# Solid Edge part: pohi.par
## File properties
Author: Andris
Template: Normal.par
Last saved by: Andris
Revision: 34
Application: Solid Edge
Face Style: Steel
Coef. of Thermal Exp: 0.0
Thermal Conductivity: 0.0
Specific Heat: 0.0
Modulus of Elasticity: 0.0
Poission's Ratio: 0.0
Yield Stress: 0.0
Ultimate Stress: 0.0
Elongation: 0.0
Accuracy: 0,990
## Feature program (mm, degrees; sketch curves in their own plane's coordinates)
make body feature "unnamed MakeBodyFeature 1"
thinwall "Thinwall_3"  Thickness = 3 mm
web network "WebNetwork_15"  Thickness = 1.5 mm
web network "WebNetwork_16"  Thickness = 1.5 mm
web network "WebNetwork_25"  Thickness = 0.25 mm
web network "WebNetwork_26"  Thickness = 0.25 mm
web network "WebNetwork_28"  Thickness = 0.25 mm
sketch for "ExtrudedCutout_6" plane through (0, 0, 24) normal (0, 0, 1) x-axis (1, 0, 0)
  bspline degree 3 poles (87.4419, -30) (113.697, -31.8378) (134.3333, -30.1711) (149.3508, -25) knots 0 1 multiplicities 4 4
  line (149.3508, 25) -> (149.3508, -25)
  bspline degree 3 poles (87.4419, 30) (113.697, 31.8378) (134.3333, 30.1711) (149.3508, 25) knots 0 1 multiplicities 4 4
  line (87.4419, 30) -> (87.4419, -30)
extrude "ExtrudedCutout_6" cut finite 34 along +normal
web network "WebNetwork_29"  Thickness = 0.25 mm
sketch for "ExtrudedProtrusion_5" plane through (0, 0, 0) normal (0, -1, 0) x-axis (1, 0, 0)
  bspline degree 3 poles (337.431, -24.5227) (338.411, -24.0381) (341.9173, -22.343) (343.844, -13.0795) (352.3372, -4.6896) (365.9993, -5.0636) (368.0449, 2.9356) (368.8697, 6.7546) knots 0 0.0636 0.2535 0.5392 0.7728 1 multiplicities 4 1 1 1 1 4
  bspline degree 3 poles (328.1156, 6.0499) (337.5399, 8.443) (351.1246, 8.6779) (368.8697, 6.7546) knots 0 1 multiplicities 4 4
  bspline degree 3 poles (328.1156, 6.0499) (320.4333, -5.77) (317.9222, -16.1755) (320.5825, -25.1666) knots 0 1 multiplicities 4 4
  bspline degree 3 poles (320.5825, -25.1666) (321.5429, -26.5521) (327.1591, -26.3375) (337.431, -24.5227) knots 0 1 multiplicities 4 4
extrude "ExtrudedProtrusion_5" add finite 4 symmetric
fillet "Round_2" radius 1
sketch for "unnamed Protrusion 1" plane through (0, 0, 22.3781) normal (0, 0, 1) x-axis (1, 0, 0)
  circle centre (349.7572, 0) radius 3.0223
extrude "unnamed Protrusion 1" add to key point along -normal
sketch for "ExtrudedCutout_9" plane through (126.5215, 0.285, 38.0033) normal (0, 0, 1) x-axis (0, 1, 0)
  line (37.215, -45.0064) -> (-37.785, -45.0064)
  line (-37.785, -45.0064) -> (-37.785, -204.2864)
  line (-37.785, -204.2864) -> (37.215, -204.2864)
  line (37.215, -204.2864) -> (37.215, -45.0064)
extrude "ExtrudedCutout_9" cut finite 0.05 along -normal
sketch for "unnamed Cutout 1" plane through (126.5215, 0.285, 38.0033) normal (0, 0, 1) x-axis (0, 1, 0)
  circle centre (-0.285, 69.0662) radius 5
extrude "unnamed Cutout 1" cut finite 13.3833 along -normal
sketch for "ExtrudedProtrusion_9" plane through (0, 0, 0) normal (0, -1, 0) x-axis (1, 0, 0)
  line (144.6164, 33.4887) -> (144.6164, 32.3387)
  line (144.6164, 32.3387) -> (143.4664, 32.3387)
  line (143.4664, 32.3387) -> (143.4664, 31.1887)
  line (143.4664, 31.1887) -> (142.3164, 31.1887)
  line (142.3164, 31.1887) -> (142.3164, 30.0387)
  line (142.3164, 30.0387) -> (141.1664, 30.0387)
  line (141.1664, 30.0387) -> (141.1664, 28.8887)
  line (141.1664, 28.8887) -> (140.0164, 28.8887)
  line (140.0164, 28.8887) -> (140.0164, 27.7387)
  line (140.0164, 27.7387) -> (138.8664, 27.7387)
  line (138.8664, 27.7387) -> (138.8664, 26.5887)
  line (138.8664, 26.5887) -> (137.7164, 26.5887)
  line (137.7164, 26.5887) -> (137.7164, 25.4387)
  line (137.7164, 25.4387) -> (136.5692, 25.3587)
  line (136.5692, 25.3587) -> (136.5692, 24.2087)
  line (136.5692, 24.2087) -> (135.4192, 24.2087)
  line (135.4192, 24.2087) -> (135.4192, 23.0587)
  line (135.4192, 23.0587) -> (134.2692, 23.0587)
  line (134.2692, 23.0587) -> (134.2692, 21.9087)
  line (134.2692, 21.9087) -> (133.1192, 21.9087)
  line (133.1192, 21.9087) -> (133.1192, 20.7587)
  line (133.1192, 20.7587) -> (131.9692, 20.7587)
  line (131.9692, 20.7587) -> (131.9692, 19.6087)
  line (131.9692, 19.6087) -> (130.8192, 19.6087)
  line (130.8192, 19.6087) -> (130.8192, 18.4587)
  line (130.8192, 18.4587) -> (129.6692, 18.4587)
  line (129.6692, 18.4587) -> (129.6692, 17.4676)
  line (129.6692, 17.4676) -> (131.8801, 17.4676)
  line (131.8801, 17.4676) -> (150.3126, 35.9237)
  line (150.3126, 35.9237) -> (150.3126, 37.7533)
  line (149.2164, 37.7533) -> (150.3126, 37.7533)
  line (149.2164, 36.9387) -> (149.2164, 37.7533)
  line (149.2164, 36.9387) -> (148.0664, 36.9387)
  line (148.0664, 36.9387) -> (148.0664, 35.7887)
  line (148.0664, 35.7887) -> (146.9164, 35.7887)
  line (146.9164, 35.7887) -> (146.9164, 34.6387)
  line (146.9164, 34.6387) -> (145.7664, 34.6387)
  line (145.7664, 34.6387) -> (145.7664, 33.4887)
  line (145.7664, 33.4887) -> (144.6164, 33.4887)
extrude "ExtrudedProtrusion_9" add finite 13.9584 symmetric
sketch for "unnamed Cutout 2" plane through (67.7189, 0, 27.0743) normal (1, 0, 0) x-axis (0, 1, 0)
  line (9.9594, 3.2497) -> (9.9594, -9.2161)
  line (9.9594, -9.2161) -> (-3.0291, -9.2161)
  line (-3.0291, -9.2161) -> (-3.0291, 3.2497)
  line (-3.0291, 3.2497) -> (9.9594, 3.2497)
extrude "unnamed Cutout 2" cut finite 8.1808 along -normal
swept protrusion "unnamed SweptProtrusion 1"
mirror "unnamed Mirror 1" of "unnamed SweptProtrusion 1" about plane through (0, 0, 0) normal (0, -1, 0)
swept protrusion "unnamed SweptProtrusion 2"
swept protrusion "unnamed SweptProtrusion 3"
mirror "unnamed Mirror 2" of "unnamed SweptProtrusion 3" about plane through (0, 0, 0) normal (0, -1, 0)
swept protrusion "unnamed SweptProtrusion 4"
swept protrusion "unnamed SweptProtrusion 5"
swept protrusion "unnamed SweptProtrusion 6"
fillet "Round_4" radius 0.1
sketch for "ExtrudedProtrusion_12" plane through (0, 0, 0) normal (0, -1, 0) x-axis (1, 0, 0)
  bspline degree 3 poles (396.5922, 55.3222) (394.4681, 54.8016) (389.5714, 53.7515) (380.5774, 51.7434) (374.6623, 53.8894) (371.442, 55.081) knots 0 0.2319 0.6336 1 multiplicities 4 1 1 4
  line (367.383, 45.995) -> (371.442, 55.081)
  bspline degree 3 poles (393.0457, 44.1347) (390.4923, 43.7584) (385.5994, 43.1851) (376.3891, 42.1056) (370.797, 44.5191) (367.383, 45.995) knots 0 0.2684 0.6132 1 multiplicities 4 1 1 4
  line (396.5922, 55.3222) -> (393.0457, 44.1347)
extrude "ExtrudedProtrusion_12" add finite 1 symmetric
fillet "Round_5" radius 1
swept protrusion "unnamed SweptProtrusion 7"
swept protrusion "unnamed SweptProtrusion 8"
sketch for "unnamed Protrusion 2" plane through (0, 0, 57.9154) normal (0, 0, 1) x-axis (1, 0, 0)
  circle centre (0, -62.5557) radius 0.25
extrude "unnamed Protrusion 2" add through along -normal
sketch for "unnamed Protrusion 3" plane through (0, 0, 57.9154) normal (0, 0, 1) x-axis (1, 0, 0)
  circle centre (-34.6227, -43.2731) radius 0.2486
extrude "unnamed Protrusion 3" add through along -normal
sketch for "unnamed Protrusion 4" plane through (0, 0, 57.9154) normal (0, 0, 1) x-axis (1, 0, 0)
  circle centre (-73.0716, -16.4479) radius 0.255
extrude "unnamed Protrusion 4" add through along -normal
sketch for "ExtrudedProtrusion_17" plane through (0, 0, 57.9154) normal (0, 0, 1) x-axis (1, 0, 0)
  circle centre (-94.4493, 0) radius 0.25
extrude "ExtrudedProtrusion_17" add finite 6.8378 along -normal
sketch for "unnamed Protrusion 5" plane through (0, 0, 57.9154) normal (0, 0, 1) x-axis (1, 0, 0)
  circle centre (-73.0716, 16.4785) radius 0.2335
extrude "unnamed Protrusion 5" add through along -normal
sketch for "unnamed Protrusion 6" plane through (0, 0, 57.9154) normal (0, 0, 1) x-axis (1, 0, 0)
  circle centre (-34.6227, 43.2659) radius 0.2421
extrude "unnamed Protrusion 6" add through along -normal
sketch for "unnamed Protrusion 7" plane through (0, 0, 57.9154) normal (0, 0, 1) x-axis (1, 0, 0)
  circle centre (0, 62.5557) radius 0.25
extrude "unnamed Protrusion 7" add through along -normal
sketch for "ExtrudedProtrusion_21" plane through (251.1679, 0, 37.9533) normal (0, 0, 1) x-axis (0, 1, 0)
  line (-26.457, -37.5232) -> (-26.457, -70.8681)
  line (-26.457, -70.8681) -> (-20.2217, -70.8681)
  line (-20.2217, -70.8681) -> (-20.2217, -37.5232)
  line (-20.2217, -37.5232) -> (-26.457, -37.5232)
extrude "ExtrudedProtrusion_21" add finite 3.4865 along +normal
sketch for "ExtrudedProtrusion_22" plane through (251.1679, 0, 37.9533) normal (0, 0, 1) x-axis (0, 1, 0)
  line (-26.457, 2.8702) -> (-26.457, -32.9146)
  line (-26.457, -32.9146) -> (-20.2217, -32.9146)
  line (-20.2217, -32.9146) -> (-20.2217, 2.8702)
  line (-20.2217, 2.8702) -> (-26.457, 2.8702)
extrude "ExtrudedProtrusion_22" add finite 4.2133 along +normal
sketch for "unnamed Cutout 3" plane through (322.0361, -23.3393, 39.6965) normal (1, 0, 0) x-axis (0, 1, 0)
  line (3.1176, 2.47) -> (-1.0195, 2.47)
  line (-1.0195, 2.47) -> (-0.5942, 0.432)
  line (-0.5942, 0.432) -> (3.1176, 0.432)
  line (3.1176, 0.432) -> (3.1176, 2.47)
extrude "unnamed Cutout 3" cut to key point along -normal
mirror "unnamed Mirror 3" of "ExtrudedProtrusion_22", "ExtrudedProtrusion_21" about plane through (0, 0, 0) normal (0, -1, 0)
extrude "unnamed Protrusion 8" add finite 3.4865
extrude "unnamed Protrusion 9" add finite 4.2133
sketch for "ExtrudedCutout_14" plane through (322.0361, 23.3393, 39.6965) normal (1, 0, 0) x-axis (0, 1, 0)
  line (-3.1176, 2.5601) -> (0.992, 2.47)
  line (0.992, 2.47) -> (0.352, -0.3474)
  line (0.352, -0.3474) -> (-3.1176, -0.3474)
  line (-3.1176, -0.3474) -> (-3.1176, 2.5601)
extrude "ExtrudedCutout_14" cut finite 77.5633 along -normal
sketch for "ExtrudedProtrusion_26" plane through (251.1679, 0, 37.9533) normal (0, 0, 1) x-axis (0, 1, 0)
  line (0, 0) -> (0, 0)
  line (-12.3838, 66.7579) -> (-12.3838, 51.8392)
  line (-12.3838, 51.8392) -> (-17.3567, 51.8392)
  line (-17.3567, 51.8392) -> (-17.3567, 70.7983)
  line (-17.3567, 70.7983) -> (14.8116, 70.7983)
  line (14.8116, 70.7983) -> (14.8116, 51.8392)
  line (14.8116, 51.8392) -> (10.4604, 51.8392)
  line (10.4604, 51.8392) -> (10.4604, 66.7579)
  line (10.4604, 66.7579) -> (-12.3838, 66.7579)
extrude "ExtrudedProtrusion_26" add finite 3.3812 along +normal
chamfer "Chamfer_3" setback 1
chamfer "Chamfer_4" setback 1
chamfer "Chamfer_5" setback 1
sketch for "ExtrudedProtrusion_27" plane through (183.9101, -0.9617, 40.8345) normal (0.707107, 0, 0.707107) x-axis (0, 1, 0)
  circle centre (-1.8733, -0.0212) radius 0.3196
extrude "ExtrudedProtrusion_27" add finite 0.3565 along +normal
sketch for "ExtrudedProtrusion_28" #1 plane through (184.1771, -2.8351, 41.0716) normal (0.707107, 0, 0.707107) x-axis (0, -1, 0)
  circle centre (0, 0) radius 2.5331
sketch for "ExtrudedProtrusion_28" #2 plane through (184.1771, -2.8351, 41.0716) normal (0.707107, 0, 0.707107) x-axis (0, -1, 0)
  arc centre (0, 0) radius 2.1861 from (-1.562, -1.5295) to (-2.1861, 0) cw
  line (-2.1861, 0) -> (-0.3136, 0)
  arc centre (0, 0) radius 0.3136 from (-0.3136, 0) to (-0.235, 0.2076) cw
  line (-0.235, 0.2076) -> (-1.6382, 1.4475)
  arc centre (0, 0) radius 2.1861 from (-1.6382, 1.4475) to (0, 2.1861) cw
  line (0, 2.1861) -> (0, 0.3136)
  line (1.562, 1.5295) -> (0.2241, 0.2194)
  arc centre (0, 0) radius 2.1861 from (1.562, 1.5295) to (2.1861, 0) cw
  line (0.3136, 0) -> (2.1861, 0)
  arc centre (0, 0) radius 0.3136 from (0.3136, 0) to (0.235, -0.2076) cw
  line (1.6382, -1.4475) -> (0.235, -0.2076)
  line (0, -0.3136) -> (0, -2.1861)
  arc centre (0, 0) radius 0.3136 from (0, -0.3136) to (-0.2241, -0.2194) cw
  line (-0.2241, -0.2194) -> (-1.562, -1.5295)
extrude "ExtrudedProtrusion_28" add finite 0.4112 along +normal
sketch used by "ExtrudedProtrusion_29" plane through (251.1679, 0, 39.789) normal (0, 0, 1) x-axis (0, 1, 0)
extrude "ExtrudedProtrusion_29" add finite 1 along +normal
sketch for "ExtrudedProtrusion_30" plane through (251.1679, 0, 39.789) normal (0, 0, 1) x-axis (0, 1, 0)
extrude "ExtrudedProtrusion_30" add finite 1 along +normal
sketch for "unnamed Protrusion 10" #1 plane through (266.1901, -14.5079, 39.789) normal (0, 0, -1) x-axis (-1, 0, 0)
  circle centre (14.8241, 0) radius 0.594
sketch for "unnamed Protrusion 10" #2 plane through (266.1901, -14.5079, 39.789) normal (0, 0, -1) x-axis (-1, 0, 0)
  circle centre (-13.1449, 0) radius 0.594
sketch for "unnamed Protrusion 10" #3 plane through (266.1901, -14.5079, 39.789) normal (0, 0, -1) x-axis (-1, 0, 0)
  circle centre (-26.2635, 0) radius 0.594
sketch for "unnamed Protrusion 10" #4 plane through (266.1901, -14.5079, 39.789) normal (0, 0, -1) x-axis (-1, 0, 0)
  circle centre (-54.2325, 0) radius 0.594
extrude "unnamed Protrusion 10" add through along +normal
mirror "unnamed Mirror 4" of "ExtrudedProtrusion_30" about plane through (0, 0, 0) normal (0, -1, 0)
extrude "unnamed Protrusion 11" add finite 1
mirror "unnamed Mirror 5" of "unnamed Protrusion 10" about plane through (0, 0, 0) normal (0, -1, 0)
extrude "unnamed Protrusion 12" add through
mirror "unnamed Mirror 6" of "ExtrudedProtrusion_29" about plane through (0, 0, 0) normal (0, -1, 0)
extrude "unnamed Protrusion 13" add finite 1
sketch used by "unnamed Cutout 4" plane through (315.6066, 0, 0) normal (1, 0, 0) x-axis (0, 1, 0)
extrude "unnamed Cutout 4" cut finite 25 along -normal
mirror "unnamed Mirror 7" of "unnamed Cutout 4" about plane through (0, 0, 0) normal (0, -1, 0)
extrude "unnamed Cutout 5" cut finite 25
sketch for "unnamed Protrusion 14" #1 plane through (315.6066, 0, 0) normal (1, 0, 0) x-axis (0, 1, 0)
  circle centre (-18.1573, 7.4973) radius 2
sketch for "unnamed Protrusion 14" #2 plane through (315.6066, 0, 0) normal (1, 0, 0) x-axis (0, 1, 0)
  circle centre (18.1573, 7.4973) radius 2
extrude "unnamed Protrusion 14" add finite 34.9716 symmetric
sketch for "unnamed Protrusion 15" plane through (333.0923, -18.1573, 7.4973) normal (1, 0, 0) x-axis (0, 1, 0)
  arc centre (0, 0) radius 5.4358 from (5.4358, 0) to (4.0074, -3.6726) cw
  line (1.4745, -1.3513) -> (4.0074, -3.6726)
  arc centre (0, 0) radius 2 from (1.4745, -1.3513) to (0, -2) cw
  line (0, -5.4358) -> (0, -2)
  arc centre (0, 0) radius 5.4358 from (0, -5.4358) to (-3.5666, -4.1021) cw
  line (-1.3123, -1.5093) -> (-3.5666, -4.1021)
  line (-5.4358, 0) -> (-2, 0)
  line (-4.0074, 3.6726) -> (-1.4745, 1.3513)
  arc centre (0, 0) radius 2 from (-1.4745, 1.3513) to (0, 2) cw
  line (0, 2) -> (0, 5.4358)
  arc centre (0, 0) radius 5.4358 from (0, 5.4358) to (3.5666, 4.1021) cw
  line (3.5666, 4.1021) -> (1.3123, 1.5093)
  arc centre (0, 0) radius 2 from (1.3123, 1.5093) to (2, 0) cw
  line (2, 0) -> (5.4358, 0)
extrude "unnamed Protrusion 15" add finite 1 along -normal
mirror "unnamed Mirror 8" of "unnamed Protrusion 15" about plane through (0, 0, 0) normal (0, -1, 0)
extrude "unnamed Protrusion 16" add finite 1
fillet "Round_10" radius 1
fillet "Round_11" radius 1
fillet "Round_14" radius 0.75
fillet "Round_15" radius 0.75
chamfer "Chamfer_7" setback 1
chamfer "Chamfer_8" setback 1
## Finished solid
Body 1: solid body, 331 faces, 823 edges, 505 vertices, 2 separate solids.
  Faces by surface: plane 204, cylinder 68, blend 20, spline 12, torus 12, swept 9, sphere 4, offset 2
  Edges by curve: line 450, circle 160, intersection 159, curve on surface 22, ellipse 17, spline 15
Body 2: solid body, 8 faces, 22 edges, 16 vertices.
  Faces by surface: spline 8
  Edges by curve: curve on surface 19, spline 3
Bounding box of the edges (mm; curved faces can reach further): 493.712 x 159.470 x 84.233, from (-97.1195, -78.9981, -26.0672) to (396.5922, 80.4718, 58.1654).
Cylindrical faces by radius (mm): R0.125 x1, R0.2335 x1, R0.2421 x1, R0.2486 x1, R0.25 x3, R0.255 x1, R0.3136 x4, R0.3196 x1, R0.35 x2, R0.375 x4, R0.594 x8, R1 x3, R2 x6, R2.1861 x4, R2.5331 x1, R3 x16, R3.0223 x2, R5 x1, R5.4358 x8
Toroidal faces (ring radius, tube radius in mm): R0.025 r0.1 x1, R0.845 r0.375 x1, R1.9122 r0.35 x2, R1.9917 r0.375 x1, R2.1636 r0.375 x4, R2.2989 r0.375 x1, R3.9881 r0.35 x2
Spherical faces by radius (mm): R1 x4
Planar faces by outward normal: +x 24, +y 17, +z 46, -x 42, -y 18, -z 11, oblique 46
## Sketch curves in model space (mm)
arc centre (333.0923, -18.1573, 7.4973) radius 2 from (333.0923, -16.6828, 6.146) through (333.0923, -17.3518, 5.6666) to (333.0923, -18.1573, 5.4973)
line (333.0923, -16.6828, 6.146) -> (333.0923, -14.1498, 3.8246)
arc centre (333.0923, -18.1573, 7.4973) radius 5.4358 from (333.0923, -12.7215, 7.4973) through (333.0923, -13.0911, 5.527) to (333.0923, -14.1498, 3.8246)
line (333.0923, -16.1573, 7.4973) -> (333.0923, -12.7215, 7.4973)
arc centre (333.0923, -18.1573, 7.4973) radius 2 from (333.0923, -16.845, 9.0066) through (333.0923, -16.3373, 8.3266) to (333.0923, -16.1573, 7.4973)
line (333.0923, -14.5907, 11.5994) -> (333.0923, -16.845, 9.0066)
arc centre (333.0923, -18.1573, 7.4973) radius 5.4358 from (333.0923, -18.1573, 12.9331) through (333.0923, -16.2534, 12.5887) to (333.0923, -14.5907, 11.5994)
line (333.0923, -18.1573, 9.4973) -> (333.0923, -18.1573, 12.9331)
arc centre (333.0923, -18.1573, 7.4973) radius 2 from (333.0923, -19.6317, 8.8486) through (333.0923, -18.9627, 9.3279) to (333.0923, -18.1573, 9.4973)
line (333.0923, -22.1647, 11.1699) -> (333.0923, -19.6317, 8.8486)
arc centre (333.0923, -18.1573, 7.4973) radius 5.4358 from (333.0923, -23.5931, 7.4973) through (333.0923, -23.2234, 9.4676) to (333.0923, -22.1647, 11.1699)
line (333.0923, -23.5931, 7.4973) -> (333.0923, -20.1573, 7.4973)
arc centre (333.0923, -18.1573, 7.4973) radius 2 from (333.0923, -19.4695, 5.988) through (333.0923, -19.9772, 6.668) to (333.0923, -20.1573, 7.4973)
line (333.0923, -19.4695, 5.988) -> (333.0923, -21.7239, 3.3952)
arc centre (333.0923, -18.1573, 7.4973) radius 5.4358 from (333.0923, -18.1573, 2.0615) through (333.0923, -20.0612, 2.4058) to (333.0923, -21.7239, 3.3952)
line (333.0923, -18.1573, 2.0615) -> (333.0923, -18.1573, 5.4973)
arc centre (281.0825, -14.9748, 39.789) radius 3 from (281.0825, -17.9748, 39.789) through (283.2647, -17.0335, 39.789) to (284.0825, -14.9748, 39.789)
line (284.0825, -14.9748, 39.789) -> (284.0825, -14.0411, 39.789)
arc centre (281.0825, -14.0411, 39.789) radius 3 from (281.0825, -11.0411, 39.789) through (283.2647, -11.9824, 39.789) to (284.0825, -14.0411, 39.789)
line (281.0825, -11.0411, 39.789) -> (251.2978, -11.0411, 39.789)
arc centre (251.2978, -14.0411, 39.789) radius 3 from (251.2978, -11.0411, 39.789) through (249.1156, -11.9824, 39.789) to (248.2978, -14.0411, 39.789)
line (248.2978, -14.0411, 39.789) -> (248.2978, -14.9748, 39.789)
arc centre (251.2978, -14.9748, 39.789) radius 3 from (251.2978, -17.9748, 39.789) through (249.1156, -17.0335, 39.789) to (248.2978, -14.9748, 39.789)
line (251.2978, -17.9748, 39.789) -> (281.0825, -17.9748, 39.789)
arc centre (290.9237, -14.9748, 39.789) radius 3 from (290.9237, -17.9748, 39.789) through (288.7416, -17.0335, 39.789) to (287.9237, -14.9748, 39.789)
line (287.9237, -14.9748, 39.789) -> (287.9237, -14.0411, 39.789)
arc centre (290.9237, -14.0411, 39.789) radius 3 from (290.9237, -11.0411, 39.789) through (288.7416, -11.9824, 39.789) to (287.9237, -14.0411, 39.789)
line (290.9237, -11.0411, 39.789) -> (320.7084, -11.0411, 39.789)
arc centre (320.7084, -14.0411, 39.789) radius 3 from (320.7084, -11.0411, 39.789) through (322.8906, -11.9824, 39.789) to (323.7084, -14.0411, 39.789)
line (323.7084, -14.0411, 39.789) -> (323.7084, -14.9748, 39.789)
arc centre (320.7084, -14.9748, 39.789) radius 3 from (320.7084, -17.9748, 39.789) through (322.8906, -17.0335, 39.789) to (323.7084, -14.9748, 39.789)
line (320.7084, -17.9748, 39.789) -> (290.9237, -17.9748, 39.789)
circle centre (320.4227, -14.5079, 39.789) radius 0.594
circle centre (292.4537, -14.5079, 39.789) radius 0.594
circle centre (251.3661, -14.5079, 39.789) radius 0.594
circle centre (279.335, -14.5079, 39.789) radius 0.594
circle centre (184.1771, -2.8351, 41.0716) radius 2.5331
arc centre (184.1771, -2.8351, 41.0716) radius 2.1861 from (183.0956, -1.2731, 42.1531) through (183.5931, -0.811, 41.6557) to (184.1771, -0.649, 41.0716)
line (184.1771, -0.649, 41.0716) -> (184.1771, -2.5215, 41.0716)
arc centre (184.1771, -2.8351, 41.0716) radius 0.3136 from (184.1771, -2.5215, 41.0716) through (184.2556, -2.5418, 40.9931) to (184.3239, -2.6001, 40.9248)
line (184.3239, -2.6001, 40.9248) -> (185.2007, -1.1968, 40.0481)
arc centre (184.1771, -2.8351, 41.0716) radius 2.1861 from (185.2007, -1.1968, 40.0481) through (185.5863, -1.9366, 39.6624) to (185.7229, -2.8351, 39.5258)
line (185.7229, -2.8351, 39.5258) -> (184.3989, -2.8351, 40.8499)
arc centre (184.1771, -2.8351, 41.0716) radius 0.3136 from (184.3989, -2.8351, 40.8499) through (184.3815, -2.9566, 40.8672) to (184.3323, -3.0591, 40.9165)
line (185.2586, -4.397, 39.9901) -> (184.3323, -3.0591, 40.9165)
arc centre (184.1771, -2.8351, 41.0716) radius 2.1861 from (185.2586, -4.397, 39.9901) through (184.7612, -4.8591, 40.4876) to (184.1771, -5.0212, 41.0716)
line (184.1771, -3.1487, 41.0716) -> (184.1771, -5.0212, 41.0716)
arc centre (184.1771, -2.8351, 41.0716) radius 0.3136 from (184.1771, -3.1487, 41.0716) through (184.0986, -3.1283, 41.1501) to (184.0303, -3.0701, 41.2184)
line (183.1536, -4.4733, 42.0952) -> (184.0303, -3.0701, 41.2184)
arc centre (184.1771, -2.8351, 41.0716) radius 2.1861 from (183.1536, -4.4733, 42.0952) through (182.7679, -3.7336, 42.4808) to (182.6313, -2.8351, 42.6174)
line (183.9554, -2.8351, 41.2933) -> (182.6313, -2.8351, 42.6174)
arc centre (184.1771, -2.8351, 41.0716) radius 0.3136 from (183.9554, -2.8351, 41.2933) through (183.9727, -2.7136, 41.276) to (184.022, -2.611, 41.2267)
line (184.022, -2.611, 41.2267) -> (183.0956, -1.2731, 42.1531)
circle centre (183.925, -2.8351, 40.8195) radius 0.3196
line (180.3696, -17.3567, 37.9533) -> (180.3696, 14.8116, 37.9533)
line (180.3696, 14.8116, 37.9533) -> (199.3287, 14.8116, 37.9533)
line (199.3287, 14.8116, 37.9533) -> (199.3287, 10.4604, 37.9533)
line (199.3287, 10.4604, 37.9533) -> (184.4101, 10.4604, 37.9533)
line (184.4101, 10.4604, 37.9533) -> (184.4101, -12.3838, 37.9533)
line (184.4101, -12.3838, 37.9533) -> (199.3287, -12.3838, 37.9533)
line (199.3287, -12.3838, 37.9533) -> (199.3287, -17.3567, 37.9533)
line (199.3287, -17.3567, 37.9533) -> (180.3696, -17.3567, 37.9533)
line (322.0361, 23.6914, 39.349) -> (322.0361, 20.2217, 39.349)
line (322.0361, 20.2217, 39.349) -> (322.0361, 20.2217, 42.2566)
line (322.0361, 20.2217, 42.2566) -> (322.0361, 24.3314, 42.1665)
line (322.0361, 24.3314, 42.1665) -> (322.0361, 23.6914, 39.349)
circle centre (337.3358, -35.199, 38.0033) radius 0.375
spline (0, 62.5557, 57.9154) -> (-41.758, 38.8672, 57.9154) -> (-94.4493, 0, 57.9154)
spline (0, -62.5557, 57.9154) -> (-41.758, -38.8672, 57.9154) -> (-94.4493, 0, 57.9154)
arc centre (337.3358, 33.2225, 39.395) radius 0.845 from (337.3358, 33.2225, 40.24) through (337.3358, 33.8364, 39.9756) to (337.3358, 34.0661, 39.3479)
arc centre (337.3358, -33.2225, 38.2483) radius 1.9917 from (337.3358, -33.2225, 40.24) through (337.3358, -34.7528, 39.523) to (337.3358, -35.199, 38.0033)
line (337.3358, -33.2225, 40.24) -> (337.3358, 33.2225, 40.24)
spline (393.0457, 0, 44.1347) -> (379.9724, 0, 42.7321) -> (367.383, 0, 45.995)
line (367.383, 0, 45.995) -> (371.442, 0, 55.081)
spline (396.5922, 0, 55.3222) -> (383.9338, 0, 52.7739) -> (371.442, 0, 55.081)
line (396.5922, 0, 55.3222) -> (393.0457, 0, 44.1347)
circle centre (0, -62.5557, 57.9154) radius 0.25
line (322.0361, -24.3588, 42.1665) -> (322.0361, -23.9336, 40.1285)
line (322.0361, -23.9336, 40.1285) -> (322.0361, -20.2217, 40.1285)
line (322.0361, -20.2217, 40.1285) -> (322.0361, -20.2217, 42.1665)
line (322.0361, -20.2217, 42.1665) -> (322.0361, -24.3588, 42.1665)
circle centre (371.1315, 0, 55.3105) radius 0.125
circle centre (-34.6227, -43.2731, 57.9154) radius 0.2486
circle centre (-73.0716, -16.4479, 57.9154) radius 0.255
circle centre (-34.6227, 43.2659, 57.9154) radius 0.2421
circle centre (-73.0716, 16.4785, 57.9154) radius 0.2335
circle centre (-94.4493, 0, 57.9154) radius 0.25
circle centre (0, -62.5557, 57.9154) radius 0.25
circle centre (0, 62.5557, 57.9154) radius 0.25
line (360.3056, 0, 30.7816) -> (371.1315, 0, 55.3105)
circle centre (85.969, 27.2573, 38.0033) radius 0.375
arc centre (85.969, -24.9593, 37.9411) radius 2.2989 from (85.969, -24.9593, 40.24) through (85.969, -26.5627, 39.5885) to (85.969, -27.2573, 38.0033)
arc centre (85.969, 24.9593, 37.9411) radius 2.2989 from (85.969, 24.9593, 40.24) through (85.969, 26.5627, 39.5885) to (85.969, 27.2573, 38.0033)
line (85.969, -25.0653, 40.24) -> (85.969, 24.9593, 40.24)
circle centre (151.954, 33.5975, 37.7533) radius 0.375
arc centre (149.8146, 33.5975, 38.0764) radius 2.1636 from (149.8146, 33.5975, 40.24) through (151.4959, 33.5975, 39.4382) to (151.954, 33.5975, 37.7533)
line (87.4198, 33.5975, 40.24) -> (149.8146, 33.5975, 40.24)
arc centre (87.439, 33.5975, 38.5665) radius 1.6736 from (87.4198, 33.5975, 40.24) through (86.0654, 33.5975, 39.5226) to (85.863, 33.5975, 38.0033)
circle centre (151.6039, -5.6438, 38.0033) radius 0.35
arc centre (149.8146, -5.6438, 38.6778) radius 1.9122 from (148.4742, -5.6438, 40.0415) through (150.9506, -5.6438, 40.216) to (151.6039, -5.6438, 38.0033)
arc centre (130.9853, -5.6438, 17.259) radius 3.9881 from (128.1897, -5.6438, 20.1032) through (127.349, -5.6438, 18.8967) to (127.0027, -5.6438, 17.4676)
line (128.1897, -5.6438, 20.1032) -> (148.4742, -5.6438, 40.0415)
circle centre (349.7572, 0, 22.3781) radius 3.0223
circle centre (349.7572, 0, 18.9582) radius 3.4797
line (330.8079, -37.5, 38.0033) -> (330.8079, 37.5, 38.0033)
line (330.8079, 37.5, 38.0033) -> (171.5279, 37.5, 38.0033)
line (171.5279, 37.5, 38.0033) -> (171.5279, -37.5, 38.0033)
line (171.5279, -37.5, 38.0033) -> (330.8079, -37.5, 38.0033)
circle centre (57.4553, 0, 38.0033) radius 5
line (363.6678, -17.406, 30.6566) -> (363.6678, 9.7279, 30.6566)
spline (337.431, 0, -24.5227) -> (352.1955, 0, -6.7116) -> (368.8697, 0, 6.7546)
spline (320.5825, 0, -25.1666) -> (325.5149, 0, -26.0447) -> (337.431, 0, -24.5227)
spline (328.1156, 0, 6.0499) -> (320.4706, 0, -10.6191) -> (320.5825, 0, -25.1666)
spline (328.1156, 0, 6.0499) -> (345.3723, 0, 8.0209) -> (368.8697, 0, 6.7546)
line (67.7189, 9.9594, 17.8581) -> (67.7189, -3.0291, 17.8581)
line (67.7189, -3.0291, 17.8581) -> (67.7189, -3.0291, 30.324)
line (67.7189, -3.0291, 30.324) -> (67.7189, 9.9594, 30.324)
line (67.7189, 9.9594, 30.324) -> (67.7189, 9.9594, 17.8581)
spline (87.4419, -30, 24) -> (122.6104, -30.1283, 24) -> (149.3508, -25, 24)
line (149.3508, 25, 24) -> (149.3508, -25, 24)
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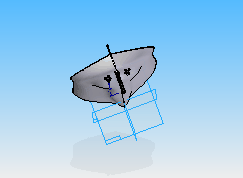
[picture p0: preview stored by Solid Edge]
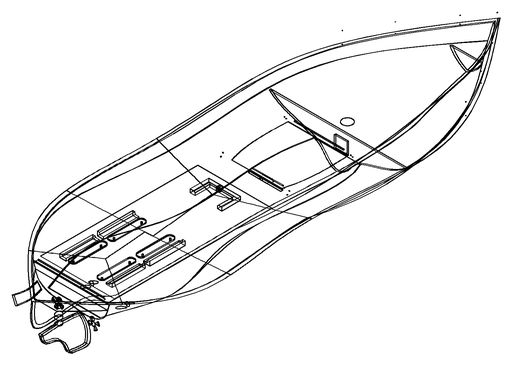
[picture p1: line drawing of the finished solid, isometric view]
